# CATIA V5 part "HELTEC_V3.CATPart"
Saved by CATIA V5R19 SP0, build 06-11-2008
Part number: HELTEC_V3
Bounding box of the stored display mesh (mm): x 12.556 to 38.056, y -5 to 1.5, z 2.265 to 54.265
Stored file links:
  C:\Users\sisca\Desktop\HELTEC_CASE\HELTEC_V3.CATPart
  C:\Program Files (x86)\Dassault Systemes\B19\intel_a\startup\materials\Italian\Catalog.CATMaterial
  C:\Program Files (x86)\Dassault Systemes\B19\intel_a\Advanced_Materials.CATMaterial
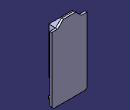
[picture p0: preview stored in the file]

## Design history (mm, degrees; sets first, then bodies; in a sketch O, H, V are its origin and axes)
Body1 (main body)
  Sketch1 on zx-plane, origin (0, 0, 0), H (-1, 0, 0), V (0, 0, 1)
    point P1 (-38.0564, 50.2652)
    line L1 (-16.8064, 50.2652) -> (-12.5564, 50.2652)
    line L2 (-12.5564, 50.2652) -> (-12.5564, 3.6794)
    line L3 (-13.9706, 2.2652) -> (-36.6422, 2.2652)
    line L4 (-38.0564, 3.6794) -> (-38.0564, 50.2652)
    point P3 (-33.8064, 54.2652)
    line L5 (-29.7937, 54.2652) -> (-20.8003, 54.2652)
    line L6 (-16.8064, 50.2712) -> (-16.8064, 50.2652)
    line L7 (-33.8064, 50.2652) -> (-33.8064, 50.2525)
    point P4 (-16.8064, 54.2652)
    line L8 (-38.0564, 50.2652) -> (-33.8064, 50.2652)
    line L9 (-16.8064, 50.2712) -> (-20.8003, 54.2652)
    line L10 (-33.8064, 50.2525) -> (-29.7937, 54.2652)
    line L11 (-12.5564, 3.6794) -> (-13.9706, 2.2652)
    line L12 (-36.6422, 2.2652) -> (-38.0564, 3.6794)
    distance L3 L1 = 48
    distance L4 L2 = 25.5
    distance L5 L3 = 52
    distance L7 L4 = 4.25
    distance P3 P4 = 17
    angle L6 L9 = 45
    length L9 = 5.6483
    angle L7 L10 = 45
    length L10 = 5.6748
    angle L2 L11 = 45
    length L11 = 2
    angle L3 L12 = 45
    length L12 = 2
    horizontal: L1 H, L3 H, L5 H, L8 H
    vertical: L2 V, L4 V, L6 V, L7 V
    coincidence: P1 L1, L6 P4, L5 P4, L7 P3, L5 P3
  Pad1: profile Sketch1, direction (0, 1, 0), length 1.5
  Sketch2 on start face of Pad1, origin (0, 0, 0), H (1, 0, 0), V (0, 0, 1)
    line L1 (16.7724, 50.1023) -> (33.7724, 50.1023)
    line L2 (33.7724, 50.1023) -> (33.7724, 17.1023)
    line L3 (33.7724, 17.1023) -> (16.7724, 17.1023)
    line L4 (16.7724, 17.1023) -> (16.7724, 50.1023)
    length L1 = 17
    length L2 = 33
    horizontal: L1 H, L3 H
    vertical: L2 V, L4 V
  Pad2: profile Sketch2, direction (0, -1, 0), length 5
  Sketch3 on face of Pad1 from Sketch1.L3, origin (0, 0, 2.2652), H (1, 0, 0), V (0, -1, 0)
    construction line L1 (22.3064, 1.5) -> (28.3064, 1.5)
    point P2 (28.3064, 1.5)
    line L2 (22.3064, 3) -> (28.3064, 3)
    line L3 (28.3064, 0) -> (22.3064, 0)
    arc A1 centre (28.3064, 1.5) radius 1.5 from (28.3064, 3) to (28.3064, 0) cw
    arc A2 centre (22.3064, 1.5) radius 1.5 from (22.3064, 0) to (22.3064, 3) cw
    reference projected line E1 (36.6422, 0) -> (13.9706, 0) from edge [start face of Pad1 | face of Pad1 from Sketch1.L3]
    reference projected line E2 (38.0564, 0) -> (38.0564, -1.5) from edge [face of Pad1 from Sketch1.L12 | face of Pad1 from Sketch1.L4]
    distance L1 L2 = 1.5
    length L1 = 6
    distance L3 E1 = 0
    distance P2 E2 = 9.75
    horizontal: L1 H
    tangency: A1 L2, A2 L2, A1 L3, A2 L3
  Pad3: profile Sketch3, direction (0, 0, 1), length 7.5
  Sketch4 on start face of Pad1, origin (0, 0, 0), H (1, 0, 0), V (0, 0, 1)
    circle A1 centre (16.5564, 6.2652) radius 2
    point P1 (16.5564, 6.2652)
    reference projected line E1 (12.5564, 3.6794) -> (12.5564, 50.2652) from edge [start face of Pad1 | face of Pad1 from Sketch1.L2]
    reference projected line E2 (36.6422, 2.2652) -> (13.9706, 2.2652) from edge [start face of Pad1 | face of Pad3]
    circle A2 centre (34.0564, 6.2652) radius 2
    point P2 (34.0564, 6.2652)
    reference projected line E3 (38.0564, 50.2652) -> (38.0564, 3.6794) from edge [start face of Pad1 | face of Pad1 from Sketch1.L4]
    reference projected line E4 (36.6422, 2.2652) -> (13.9706, 2.2652) from edge [start face of Pad1 | face of Pad3]
    radius A1 = 2
    distance E1 P1 = 4
    distance P1 E2 = 4
    radius A2 = 2
    distance P2 E3 = 4
    distance P2 E4 = 4
  Pad4: profile Sketch4, direction (0, -1, 0), length 3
